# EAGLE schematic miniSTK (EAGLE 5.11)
ALTERNATIV: BLM21PG331; ARTIKEL: ABM7-14.7456MHZ-D2Y; COPYRIGHT: © 2013 Leo-Andres Hofmann; LICENSE: CC-BY-SA 3.0; MATERIAL: NP0/C0G; PROJEKT: miniSTK; REVISION: 1.1; TEXT-1: Prototypenbereich; TEXT-2: LEDs & Taster; TEXT-3: Erweiterungsanschluss; TEXT-5: Referenzwiderstände: 1%; TOLERANZ: 1%; TP_SIGNAL_NAME: MP-1

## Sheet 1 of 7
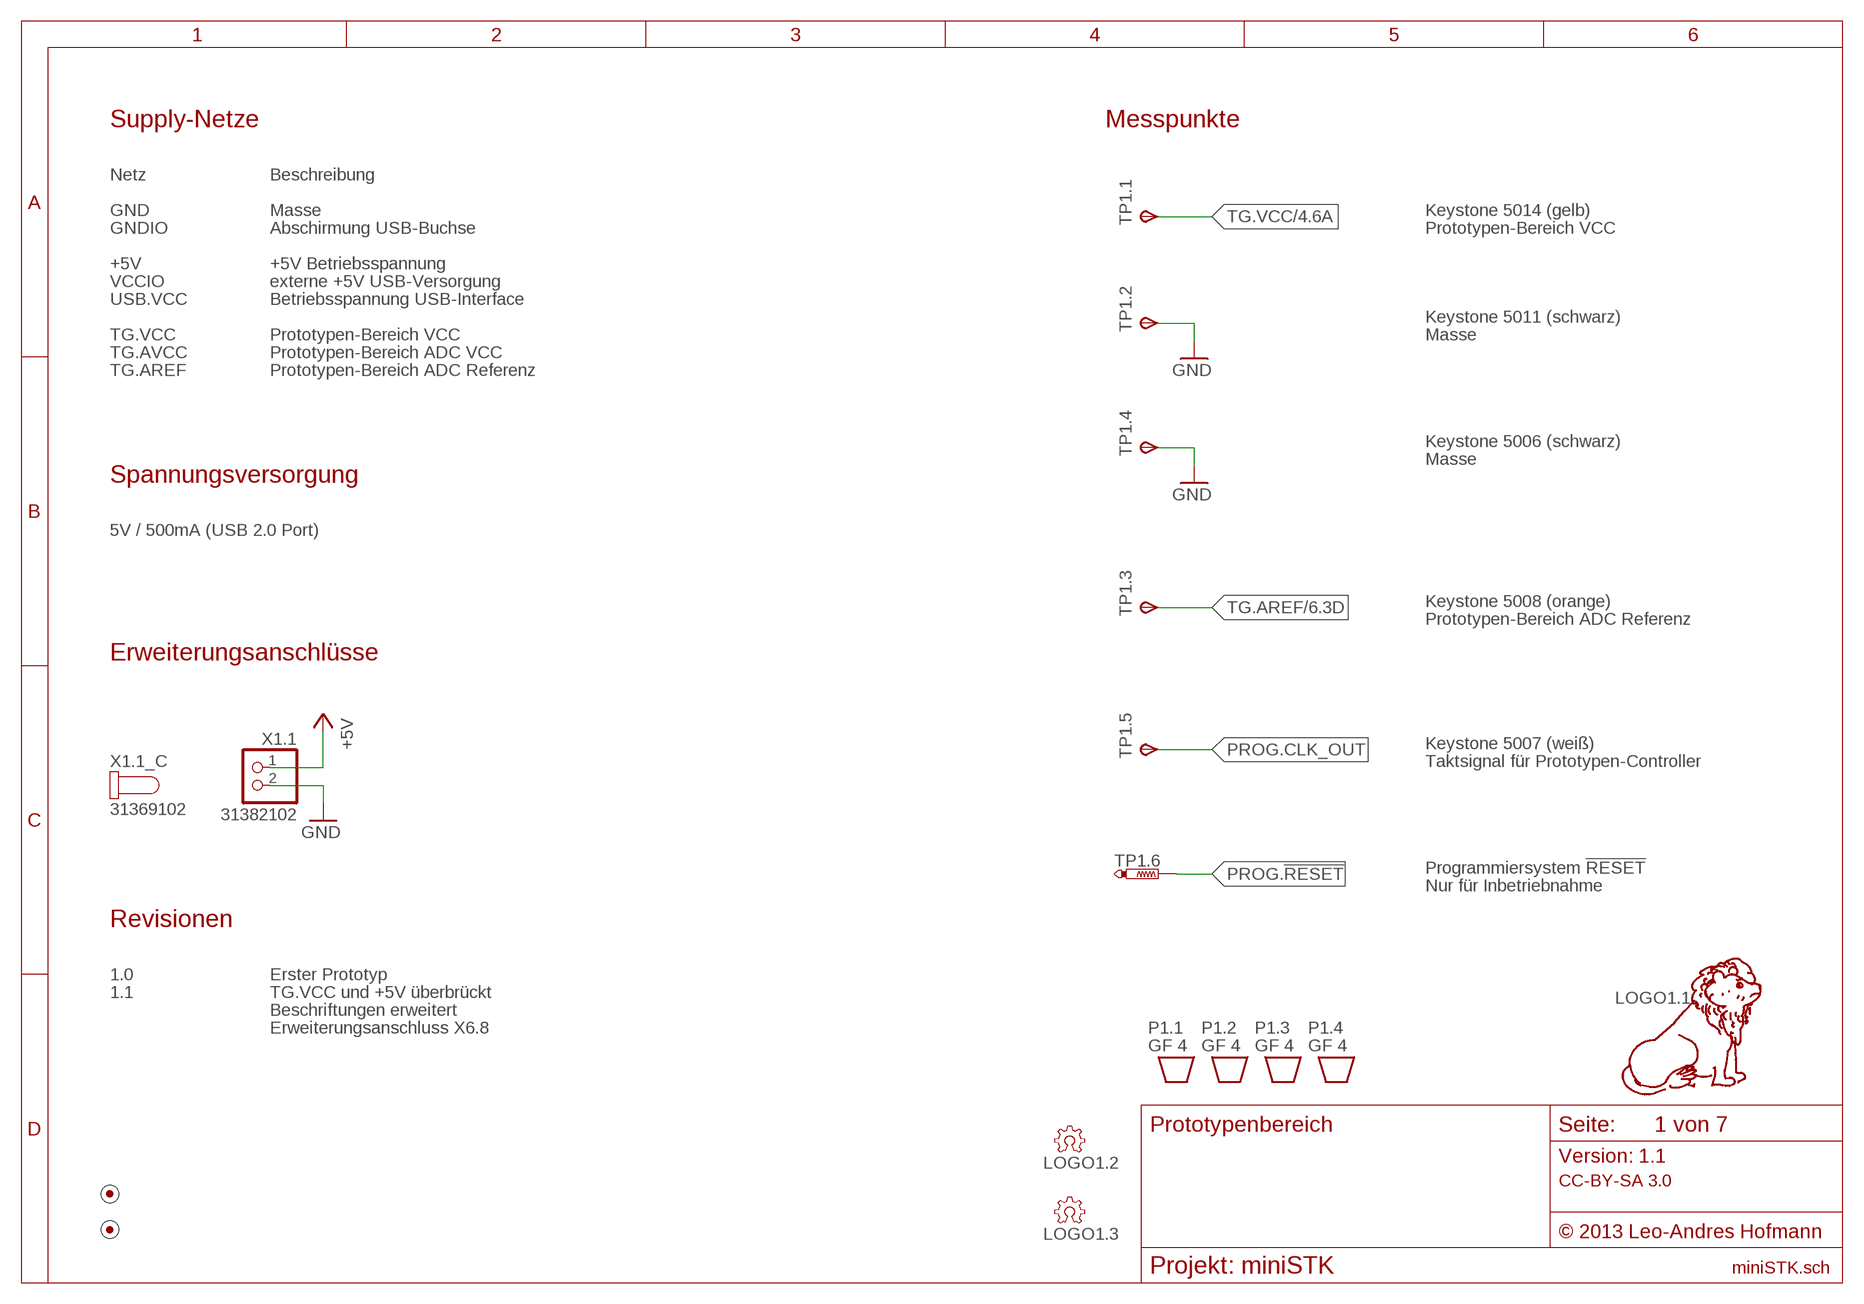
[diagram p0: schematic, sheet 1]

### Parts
LOGO1.1  LOGO-10MM-TPLACE  [10MM-TPLACE]
LOGO1.2  OSHW-3MM-FILL-TSTOP  [OSHW-FILL-3MM-TSTOP]
LOGO1.3  OSHW-3MM-FILL-TPLACE  [OSHW-FILL-3MM-TPLACE]
MARK1  FIDUCIAL-1.0/CREAM  [FIDUCIAL-1MM/CREAM]
MARK2  FIDUCIAL-1.0/CREAM  [FIDUCIAL-1MM/CREAM]
P1.1  GF 4  PAD/GF_4/REF  [FOOT-12MM/REF]
P1.2  GF 4  PAD/GF_4/REF  [FOOT-12MM/REF]
P1.3  GF 4  PAD/GF_4/REF  [FOOT-12MM/REF]
P1.4  GF 4  PAD/GF_4/REF  [FOOT-12MM/REF]
TP1.1  5014  TESTPOINT-1.6MM  [TESTPOINT-1.6MM]
TP1.2  5011  TESTPOINT-1.6MM  [TESTPOINT-1.6MM]
TP1.3  5008  TESTPOINT-1.6MM  [TESTPOINT-1.6MM]
TP1.4  5006  TESTPOINT-1.6MM  [TESTPOINT-1.6MM]
TP1.5  5007  TESTPOINT-1.6MM  [TESTPOINT-1.6MM]
TP1.6  PTR1TP15R  [TP15R]
X1.1  31382102  1PIN-2-31382102  [31382102]

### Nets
+5V: X1.1.1 ; also sheet 2,3,4,5,6,7
GND: TP1.2.TP(PP) TP1.4.TP(PP) X1.1.2 ; also sheet 2,3,4,5,6,7
PROG.!RESET: TP1.6.TP ; also sheet 4
PROG.CLK_OUT [Taktsignale]: TP1.5.TP(PP) ; also sheet 4
TG.AREF: TP1.3.TP(PP) ; also sheet 6
TG.VCC: TP1.1.TP(PP) ; also sheet 4,5,6,7

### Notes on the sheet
- Supply-Netze | Messpunkte
- Netz | Beschreibung
- GND | Masse | Keystone 5014 (gelb)
- GNDIO | Abschirmung USB-Buchse | Prototypen-Bereich VCC
- +5V | +5V Betriebsspannung
- VCCIO | externe +5V USB-Versorgung
- USB.VCC | Betriebsspannung USB-Interface
- Keystone 5011 (schwarz)
- TG.VCC | Prototypen-Bereich VCC | Masse
- TG.AVCC | Prototypen-Bereich ADC VCC
- TG.AREF | Prototypen-Bereich ADC Referenz
- Keystone 5006 (schwarz)
- Masse
- Spannungsversorgung
- 5V / 500mA (USB 2.0 Port)
- Keystone 5008 (orange)
- Prototypen-Bereich ADC Referenz
- Erweiterungsanschlüsse
- Keystone 5007 (weiß)
- Taktsignal für Prototypen-Controller
- Programmiersystem !RESET
- Nur für Inbetriebnahme
- Revisionen
- 1.0 | Erster Prototyp
- 1.1 | TG.VCC und +5V überbrückt
- Beschriftungen erweitert
- Erweiterungsanschluss X6.8

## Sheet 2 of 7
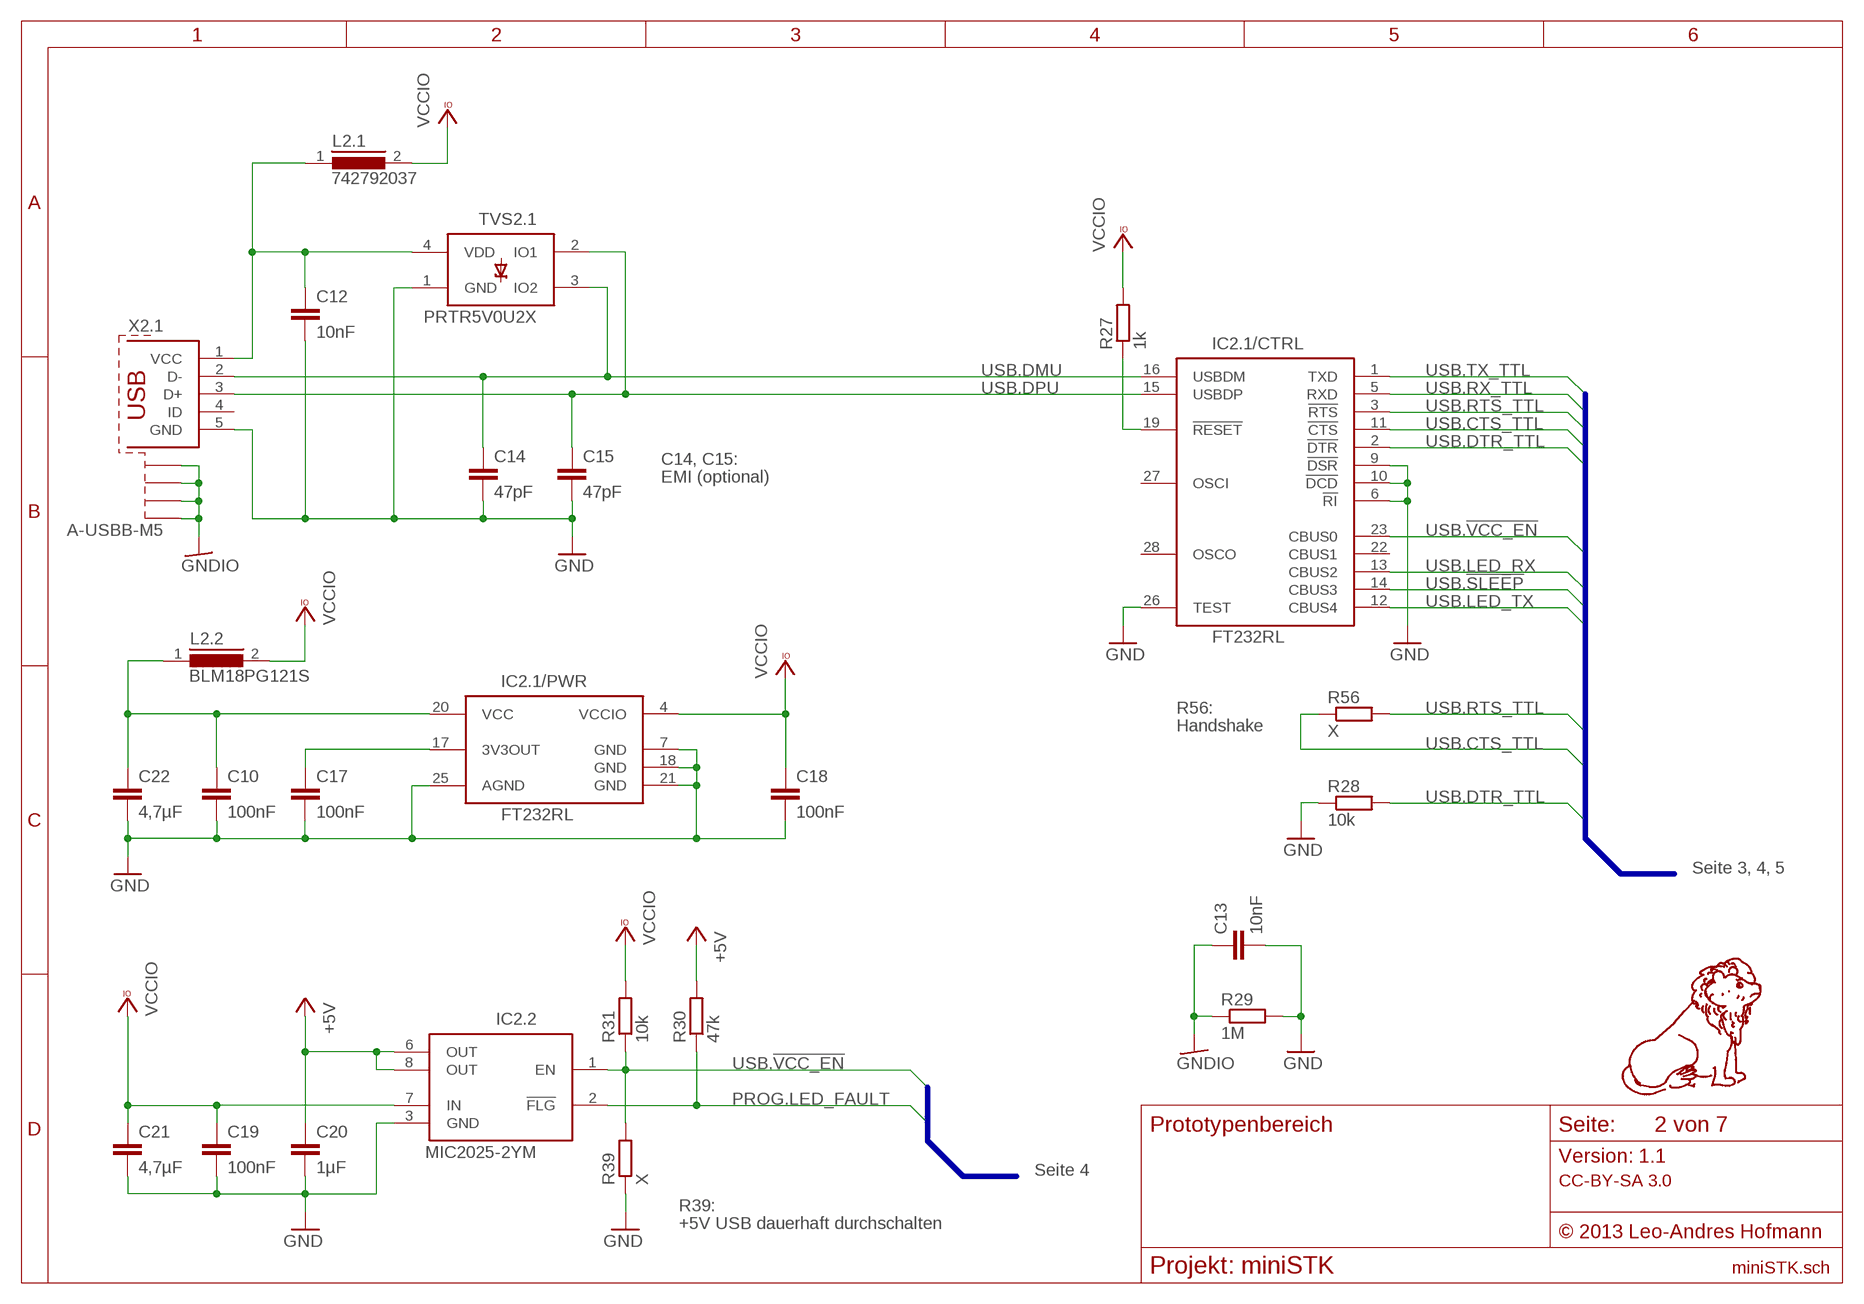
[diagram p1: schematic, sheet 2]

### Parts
C10  100nF  C-0603  [C-0603]
C12  10nF  C-0805  [C-0805]
C13  10nF  C-0805  [C-0805]
C14  47pF  C-0603  [C-0603]
C15  47pF  C-0603  [C-0603]
C17  100nF  C-0603  [C-0603]
C18  100nF  C-0603  [C-0603]
C19  100nF  C-0603  [C-0603]
C20  1µF  C-0603  [C-0603]
C21  4,7µF  C-0805  [C-0805]
C22  4,7µF  C-0805  [C-0805]
IC2.1  FT232RL  [SSOP28]
IC2.2  MIC2025-2YM  MIC2025-XYM  [SOIC8]
L2.1  742792037  INDUCTOR-WE-CBF-0805  [WE-CBF-0805]
L2.2  BLM18PG121S  INDUCTOR-BLM18  [BLM18]
R27  1k  R-0603  [R-0603]
R28  10k  R-0603  [R-0603]
R29  1M  R-0805  [R-0805]
R30  47k  R-0603  [R-0603]
R31  10k  R-0603  [R-0603]
R39  X  R-0603  [R-0603]
R56  X  R-0603  [R-0603]
TVS2.1  PRTR5V0U2X  2-ARRAY-NXP-PRTR  [SOT143B]
X2.1  A-USBB-M5  A-USBB-M5/SMD  [MINI-USB-B-SMD]

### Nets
3V3OUT: C17.1 IC2.1.17(/PWR:3V3OUT)
+5V: C20.1 IC2.2.6(OUT) IC2.2.8(OUT) R30.2 ; also sheet 1,3,4,5,6,7
GND: C10.2 C12.2 C13.2 C14.2 C15.2 C17.2 C18.2 C19.2 C20.2 C21.2 C22.2 IC2.1.6(/CTRL:!RI) IC2.1.7(/PWR:GND) IC2.1.9(/CTRL:!DSR) IC2.1.10(/CTRL:!DCD) IC2.1.18(/PWR:GND) IC2.1.21(/PWR:GND) IC2.1.25(/PWR:AGND) IC2.1.26(/CTRL:TEST) IC2.2.3(GND) R28.1 R29.2 R39.1 TVS2.1.1(GND) X2.1.5(GND) ; also sheet 1,3,4,5,6,7
GNDIO [IO-Schirm]: C13.1 R29.1 X2.1.S1(SHIELD) X2.1.S2(SHIELD) X2.1.S3(SHIELD) X2.1.S4(SHIELD)
IC2.1/!RESET: IC2.1.19(/CTRL:!RESET) R27.1
N$25: C12.1 L2.1.1 TVS2.1.4(VDD) X2.1.1(VCC)
PROG.LED_FAULT: IC2.2.2(!FLG) R30.1 ; also sheet 4,5
USB.!SLEEP: IC2.1.14(/CTRL:CBUS3) ; also sheet 5
USB.!VCC_EN: IC2.1.23(/CTRL:CBUS0) IC2.2.1(EN) R31.1 R39.2
USB.CTS_TTL: IC2.1.11(/CTRL:!CTS) R56.1 ; also sheet 5
USB.DMU [USB Datenleitungen]: C14.1 IC2.1.16(/CTRL:USBDM) TVS2.1.3(IO2) X2.1.2(D-)
USB.DPU [USB Datenleitungen]: C15.1 IC2.1.15(/CTRL:USBDP) TVS2.1.2(IO1) X2.1.3(D+)
USB.DTR_TTL: IC2.1.2(/CTRL:!DTR) R28.2 ; also sheet 4
USB.LED_RX: IC2.1.13(/CTRL:CBUS2) ; also sheet 5
USB.LED_TX: IC2.1.12(/CTRL:CBUS4) ; also sheet 5
USB.RTS_TTL: IC2.1.3(/CTRL:!RTS) R56.2 ; also sheet 5
USB.RX_TTL: IC2.1.5(/CTRL:RXD) ; also sheet 3
USB.TX_TTL: IC2.1.1(/CTRL:TXD) ; also sheet 3
USB.VCC: C10.1 C22.1 IC2.1.20(/PWR:VCC) L2.2.1
VCCIO: C18.1 C19.1 C21.1 IC2.1.4(/PWR:VCCIO) IC2.2.7(IN) L2.1.2 L2.2.2 R27.2 R31.2 ; also sheet 4,5
Unconnected: IC2.1.22(/CTRL:CBUS1) IC2.1.27(/CTRL:OSCI) IC2.1.28(/CTRL:OSCO) X2.1.4(ID)

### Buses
USB:USB.TX_TTL,USB.RX_TTL,USB.RTS_TTL,USB.CTS_TTL,USB.DTR_TTL,USB.!VCC_EN,USB.!SLEEP,USB.LED_TX,USB.LED_RX
USB:USB.!VCC_EN,PROG.LED_FAULT

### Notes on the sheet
- C14, C15:
- EMI (optional)
- R56:
- Handshake
- Seite 3, 4, 5
- Seite 4
- R39:
- +5V USB dauerhaft durchschalten

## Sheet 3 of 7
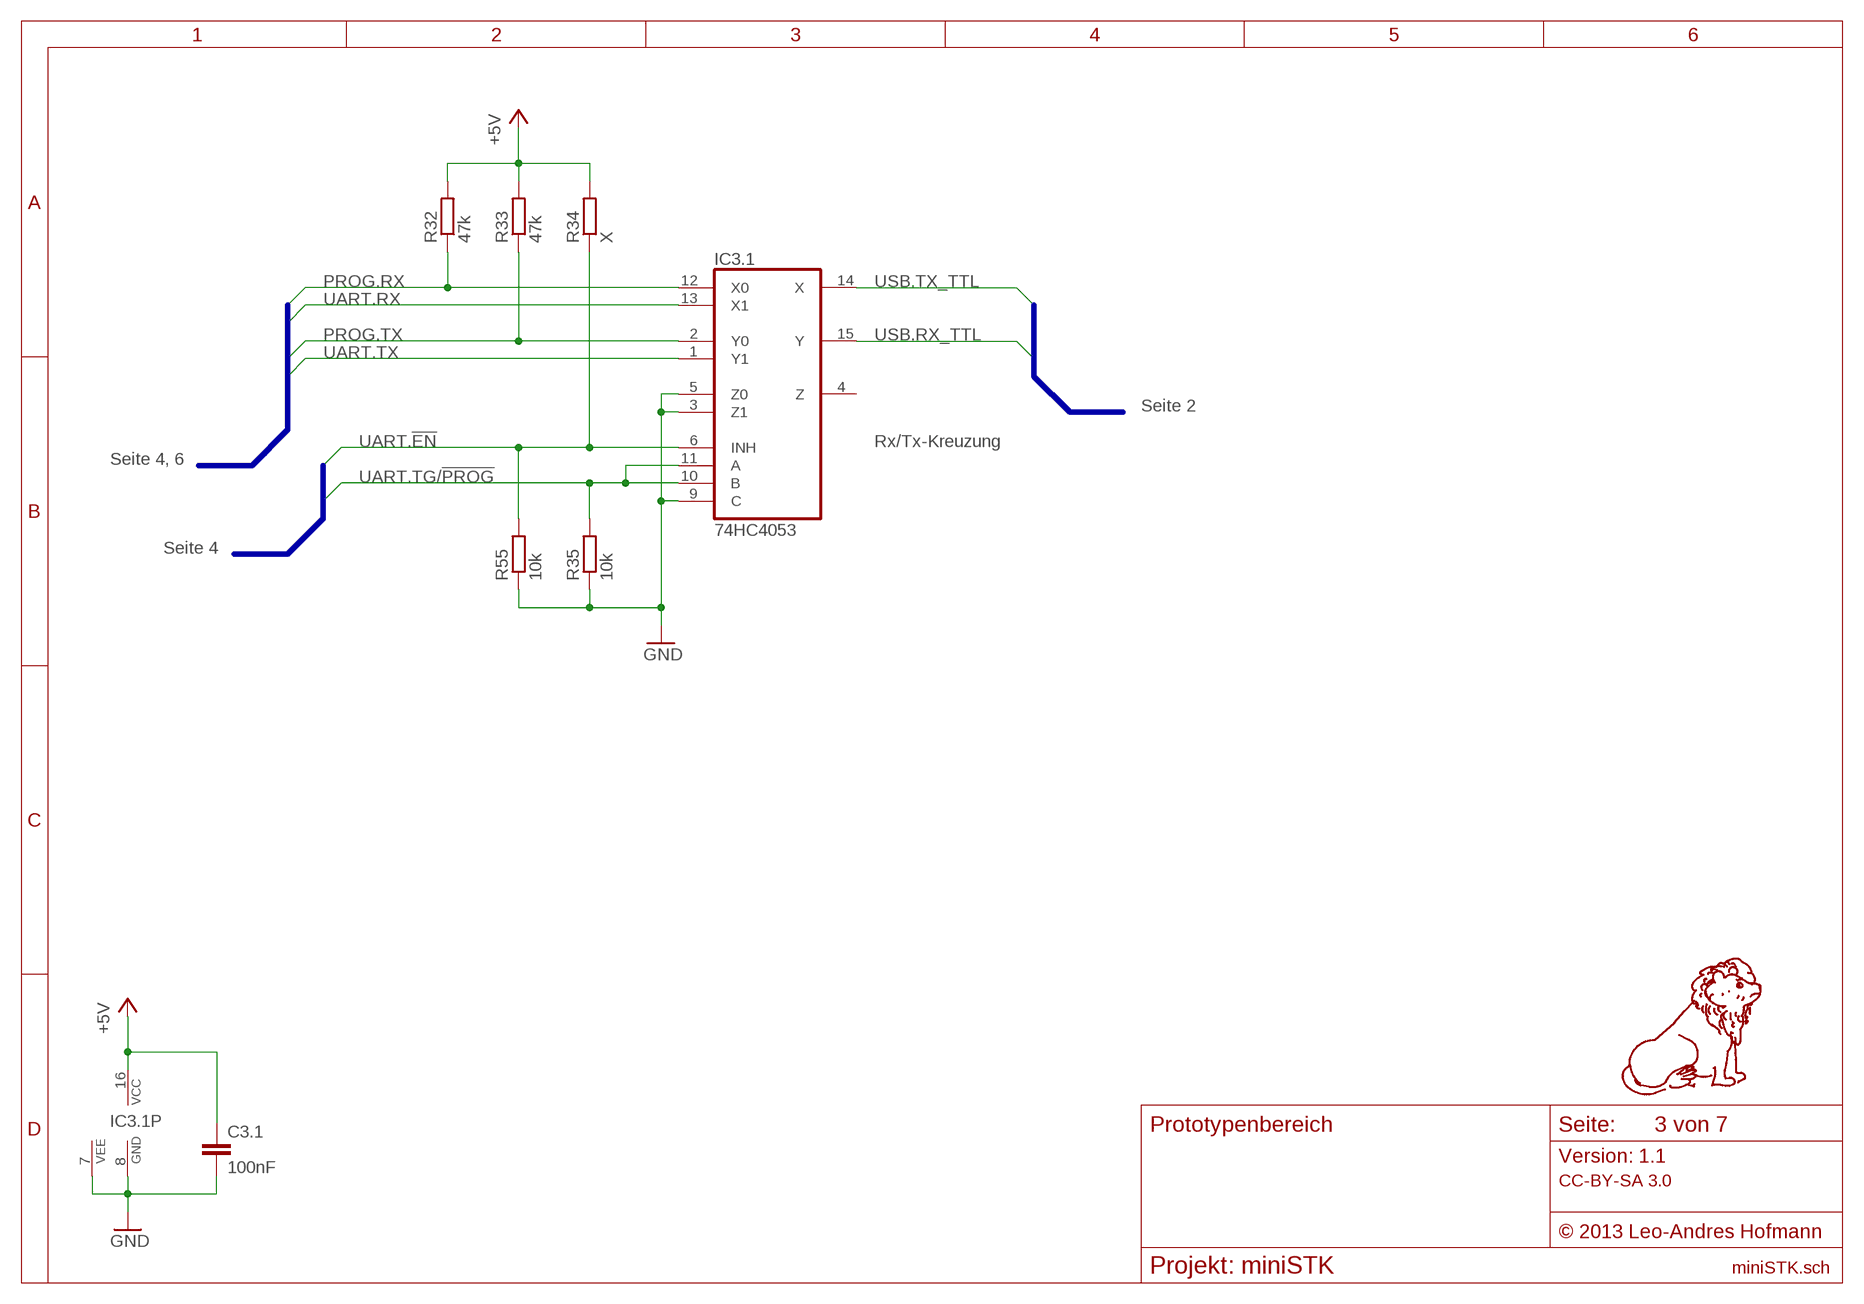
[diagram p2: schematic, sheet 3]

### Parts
C3.1  100nF  C-0603  [C-0603]
IC3.1  74HC4053  4053D  [SO16]
R32  47k  R-0603  [R-0603]
R33  47k  R-0603  [R-0603]
R34  X  R-0603  [R-0603]
R35  10k  R-0603  [R-0603]
R55  10k  R-0603  [R-0603]

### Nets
+5V: C3.1.1 IC3.1.16(VCC) R32.2 R33.2 R34.2 ; also sheet 1,2,4,5,6,7
GND: C3.1.2 IC3.1.3(Z1) IC3.1.5(Z0) IC3.1.7(VEE) IC3.1.8(GND) IC3.1.9(C) R35.1 R55.1 ; also sheet 1,2,4,5,6,7
PROG.RX: IC3.1.12(X0) R32.1 ; also sheet 4
PROG.TX: IC3.1.2(Y0) R33.1 ; also sheet 4
UART.!EN: IC3.1.6(INH) R34.1 R55.2 ; also sheet 4
UART.RX: IC3.1.13(X1) ; also sheet 6
UART.TG/!PROG: IC3.1.10(B) IC3.1.11(A) R35.2 ; also sheet 4
UART.TX: IC3.1.1(Y1) ; also sheet 6
USB.RX_TTL: IC3.1.15(Y) ; also sheet 2
USB.TX_TTL: IC3.1.14(X) ; also sheet 2
Unconnected: IC3.1.4(Z)

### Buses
USB:USB.TX_TTL,USB.RX_TTL
UART:UART.!EN,UART.TG/!PROG
UART:PROG.RX,PROG.TX,UART.RX,UART.TX

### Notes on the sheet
- Seite 2
- Rx/Tx-Kreuzung
- Seite 4, 6
- Seite 4

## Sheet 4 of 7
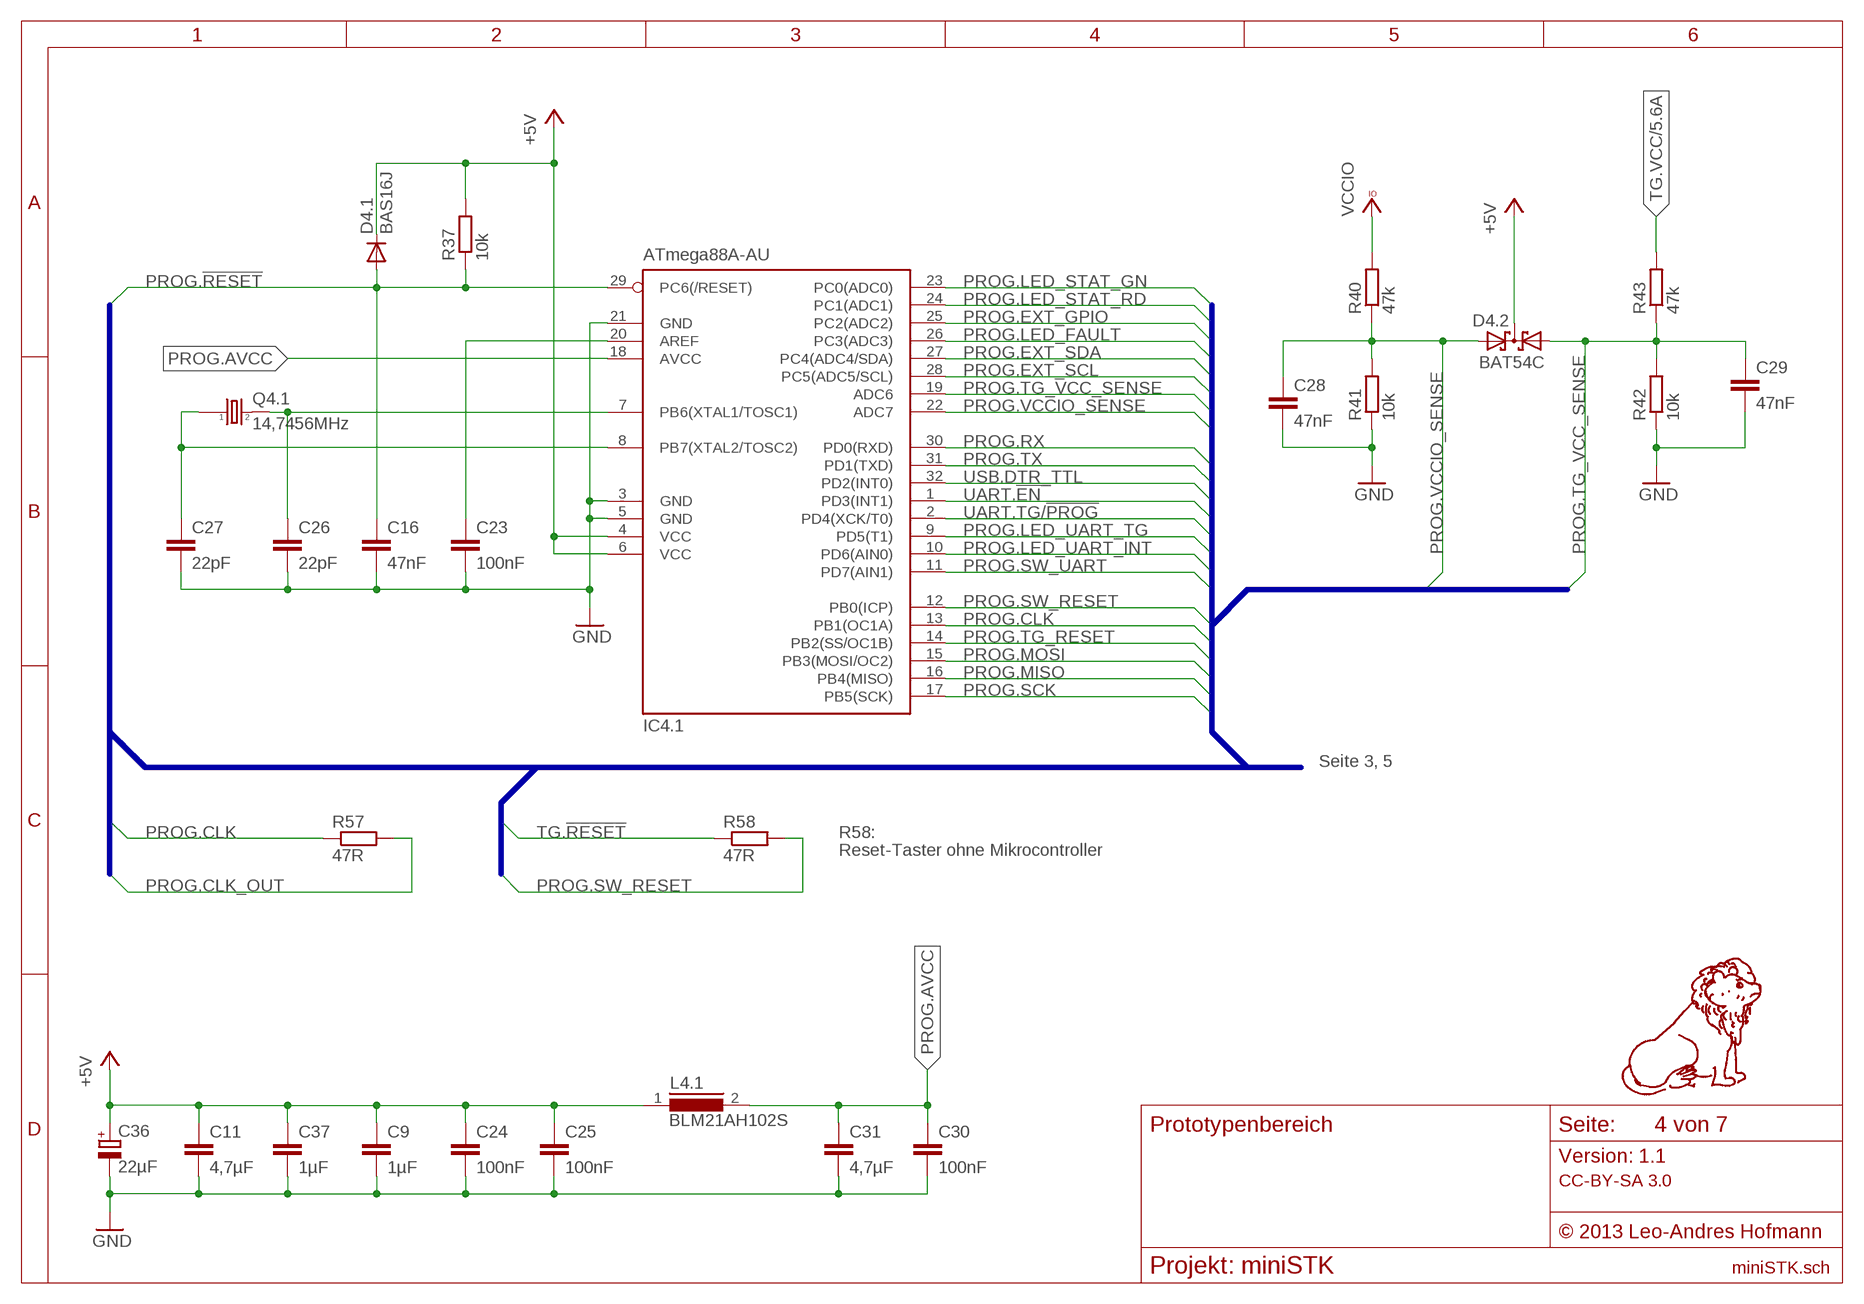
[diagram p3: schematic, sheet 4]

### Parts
C9  1µF  C-0603  [C-0603]
C11  4,7µF  C-0805  [C-0805]
C16  47nF  C-0603  [C-0603]
C23  100nF  C-0603  [C-0603]
C24  100nF  C-0603  [C-0603]
C25  100nF  C-0603  [C-0603]
C26  22pF  C-0603  [C-0603]
C27  22pF  C-0603  [C-0603]
C28  47nF  C-0603  [C-0603]
C29  47nF  C-0603  [C-0603]
C30  100nF  C-0603  [C-0603]
C31  4,7µF  C-0805  [C-0805]
C36  22µF  CPOL-EUB  [PANASONIC_B]
C37  1µF  C-0603  [C-0603]
D4.1  BAS16J  DIODE-SOD323  [DIODE-SOD323]
D4.2  BAT54C  [SOT23]
IC4.1  ATmega88A-AU  MEGA8-AI  [TQFP32-08]
L4.1  BLM21AH102S  INDUCTOR-BLM21  [BLM21]
Q4.1  14,7456MHz  CRYSTAL-ABM7  [CRYSTAL-ABM7]
R37  10k  R-0603  [R-0603]
R40  47k  R-0603  [R-0603]
R41  10k  R-0603  [R-0603]
R42  10k  R-0603  [R-0603]
R43  47k  R-0603  [R-0603]
R57  47R  R-0603  [R-0603]
R58  47R  R-0603  [R-0603]

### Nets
+5V: C9.1 C11.1 C24.1 C25.1 C36.+ C37.1 D4.1.C D4.2.3(CC) IC4.1.4(VCC) IC4.1.6(VCC) L4.1.1 R37.2 ; also sheet 1,2,3,5,6,7
GND: C9.2 C11.2 C16.2 C23.2 C24.2 C25.2 C26.2 C27.2 C28.2 C29.2 C30.2 C31.2 C36.- C37.2 IC4.1.3(GND) IC4.1.5(GND) IC4.1.21(GND) R41.1 R42.1 ; also sheet 1,2,3,5,6,7
N$28: C26.1 IC4.1.7(PB6(XTAL1/TOSC1)) Q4.1.2
N$29: C23.1 IC4.1.20(AREF)
N$30: C27.1 IC4.1.8(PB7(XTAL2/TOSC2)) Q4.1.1
PROG.!RESET: C16.1 D4.1.A IC4.1.29(PC6(/RESET)) R37.1 ; also sheet 1
PROG.AVCC: C30.1 C31.1 IC4.1.18(AVCC) L4.1.2
PROG.CLK [Taktsignale]: IC4.1.13(PB1(OC1A)) R57.1
PROG.CLK_OUT [Taktsignale]: R57.2 ; also sheet 1
PROG.EXT_GPIO: IC4.1.25(PC2(ADC2)) ; also sheet 5
PROG.EXT_SCL: IC4.1.28(PC5(ADC5/SCL)) ; also sheet 5
PROG.EXT_SDA: IC4.1.27(PC4(ADC4/SDA)) ; also sheet 5
PROG.LED_FAULT: IC4.1.26(PC3(ADC3)) ; also sheet 2,5
PROG.LED_STAT_GN: IC4.1.23(PC0(ADC0)) ; also sheet 5
PROG.LED_STAT_RD: IC4.1.24(PC1(ADC1)) ; also sheet 5
PROG.LED_UART_INT: IC4.1.10(PD6(AIN0)) ; also sheet 5
PROG.LED_UART_TG: IC4.1.9(PD5(T1)) ; also sheet 5
PROG.MISO: IC4.1.16(PB4(MISO)) ; also sheet 5
PROG.MOSI: IC4.1.15(PB3(MOSI/OC2)) ; also sheet 5
PROG.RX: IC4.1.30(PD0(RXD)) ; also sheet 3
PROG.SCK: IC4.1.17(PB5(SCK)) ; also sheet 5
PROG.SW_RESET: IC4.1.12(PB0(ICP)) R58.2 ; also sheet 5
PROG.SW_UART: IC4.1.11(PD7(AIN1)) ; also sheet 5
PROG.TG_RESET: IC4.1.14(PB2(SS/OC1B)) ; also sheet 5
PROG.TG_VCC_SENSE: C29.1 D4.2.1(A1) IC4.1.19(ADC6) R42.2 R43.1
PROG.TX: IC4.1.31(PD1(TXD)) ; also sheet 3
PROG.VCCIO_SENSE: C28.1 D4.2.2(A2) IC4.1.22(ADC7) R40.1 R41.2
TG.!RESET: R58.1 ; also sheet 5,6
TG.VCC: R43.2 ; also sheet 1,5,6,7
UART.!EN: IC4.1.1(PD3(INT1)) ; also sheet 3
UART.TG/!PROG: IC4.1.2(PD4(XCK/T0)) ; also sheet 3
USB.DTR_TTL: IC4.1.32(PD2(INT0)) ; also sheet 2
VCCIO: R40.2 ; also sheet 2,5

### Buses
PROG:PROG.!RESET,PROG.RX,PROG.TX,USB.!VCC_FAULT,USB.DTR_TTL,UART.!EN,UART.TG/!PROG,PROG.MOSI,PROG.MISO,PROG.SCK,PROG.TG_RESET,PROG.VCCIO_SENSE,PROG.TG_VCC_SENSE,PROG.CLK,PROG.SW_UART,PROG.SW_RESET,PROG.EXT_SDA,PROG.EXT_SCL,PROG.EXT_GPIO,PROG.LED_STAT_RD,PROG.LED_STAT_GN,PROG.LED_UART_TG,PROG.LED_UART_INT,PROG.LED_FAULT,PROG.CLK_OUT,TG.!RESET

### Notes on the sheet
- Seite 3, 5
- R58:
- Reset-Taster ohne Mikrocontroller

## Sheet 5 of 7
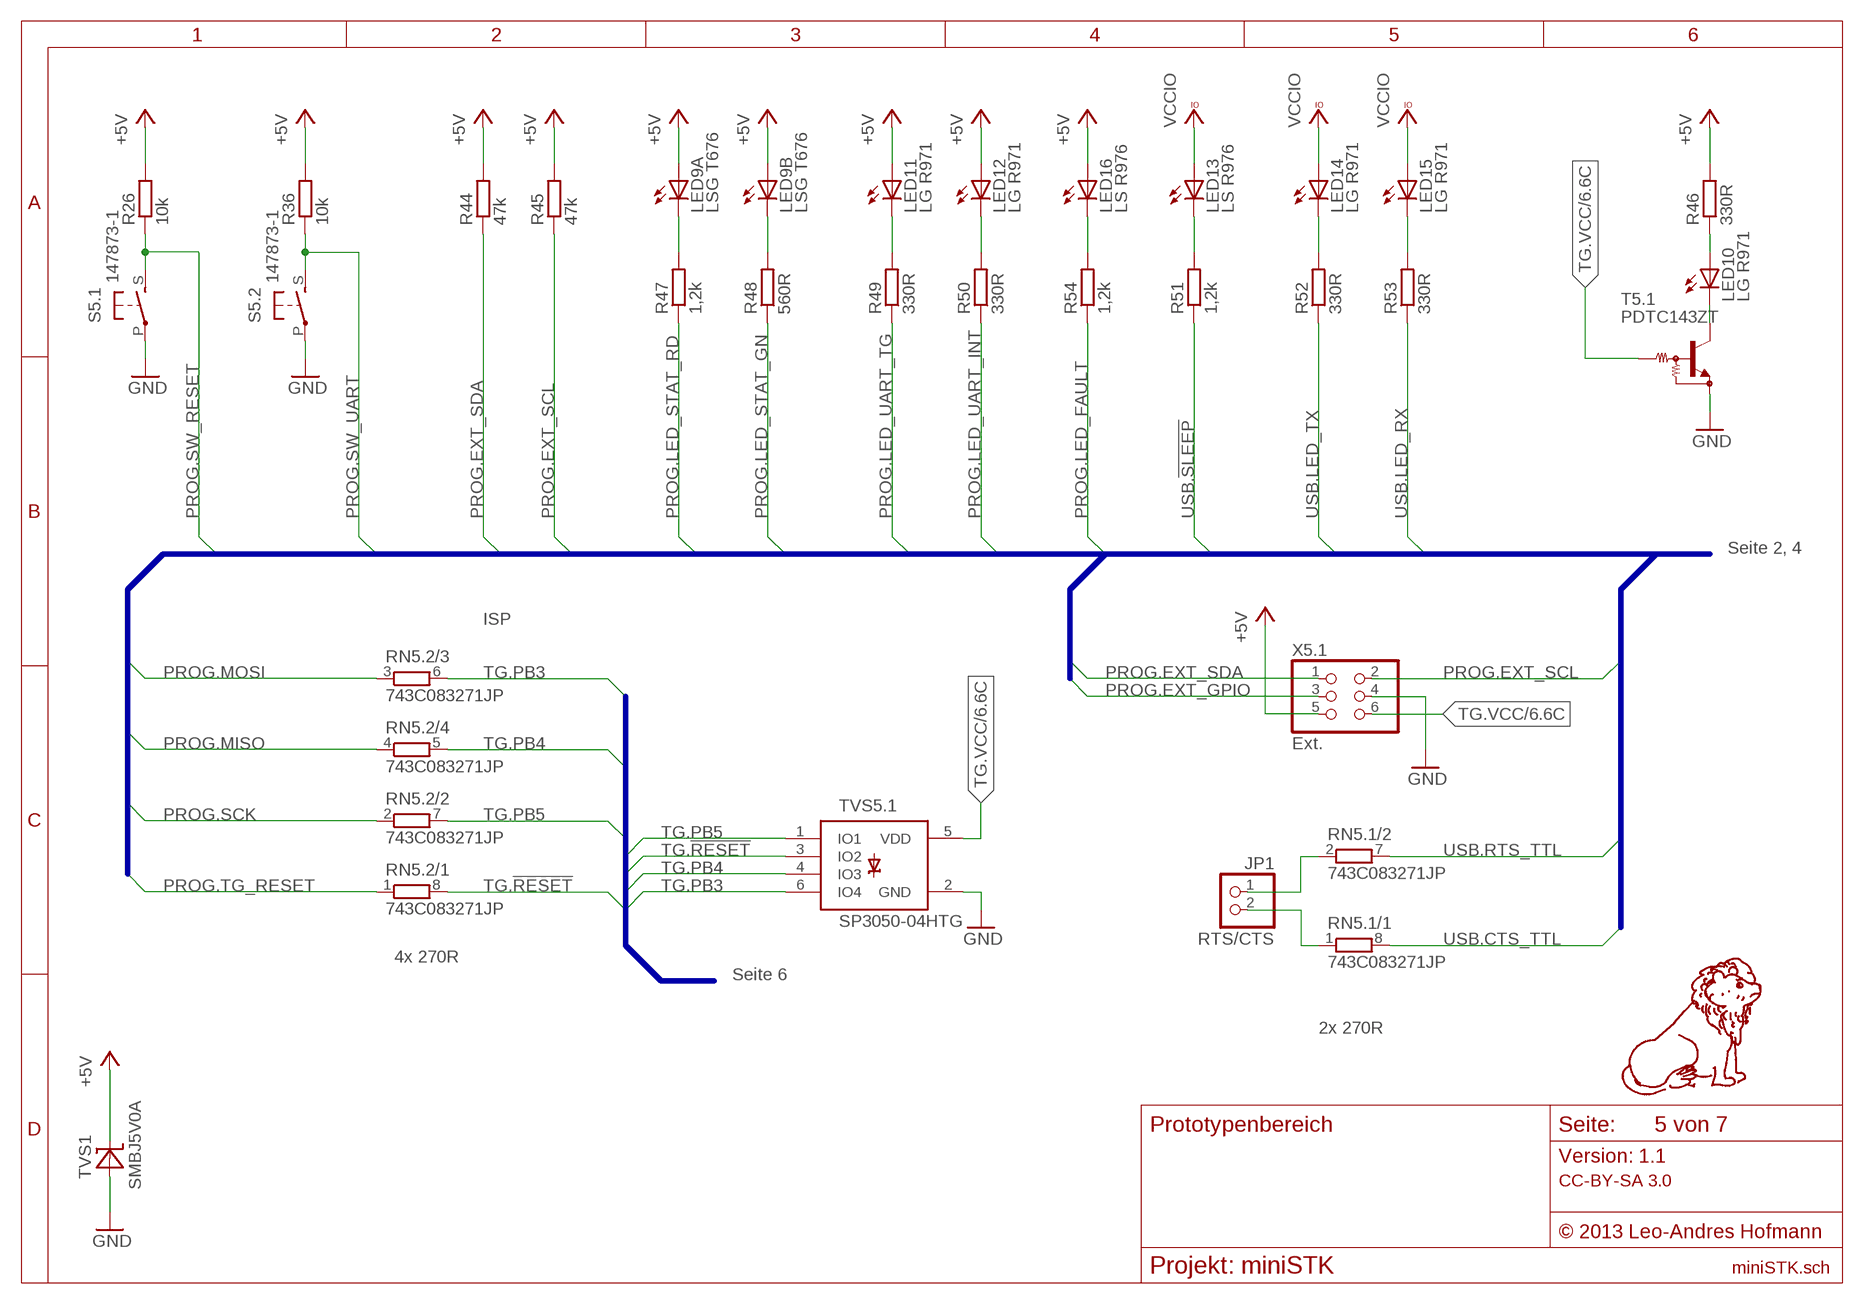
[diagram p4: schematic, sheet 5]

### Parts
JP1  RTS/CTS  PINHD-1X2  [1X02]
LED9  LSG T676  LED-DUO-TOPLED-DUO-S  [OSRAM-TOPLED_2-S]
LED10  LG R971  LED-CHIPLED-0805  [CHIPLED-0805]
LED11  LG R971  LED-CHIPLED-0805  [CHIPLED-0805]
LED12  LG R971  LED-CHIPLED-0805  [CHIPLED-0805]
LED13  LS R976  LED-CHIPLED-0805  [CHIPLED-0805]
LED14  LG R971  LED-CHIPLED-0805  [CHIPLED-0805]
LED15  LG R971  LED-CHIPLED-0805  [CHIPLED-0805]
LED16  LS R976  LED-CHIPLED-0805  [CHIPLED-0805]
R26  10k  R-0603  [R-0603]
R36  10k  R-0603  [R-0603]
R44  47k  R-0603  [R-0603]
R45  47k  R-0603  [R-0603]
R46  330R  R-0603  [R-0603]
R47  1,2k  R-0603  [R-0603]
R48  560R  R-0603  [R-0603]
R49  330R  R-0603  [R-0603]
R50  330R  R-0603  [R-0603]
R51  1,2k  R-0603  [R-0603]
R52  330R  R-0603  [R-0603]
R53  330R  R-0603  [R-0603]
R54  1,2k  R-0603  [R-0603]
RN5.1  743C083271JP  RN4I-CTS_743C083  [743C083]
RN5.2  743C083271JP  RN4I-CTS_743C083  [743C083]
S5.1  147873-1  SWITCH-147873  [SWITCH-147873]
S5.2  147873-1  SWITCH-147873  [SWITCH-147873]
T5.1  PDTC143ZT  MUN2211T1-NPN_DRIVER-SC59-BEC  [SC59-BEC]
TVS1  SMBJ5V0A  TVS-UNI-SM6T-X-A  [DO214-AA]
TVS5.1  SP3050-04HTG  4-ARRAY-SP3050-04H  [SOT23-6_2]
X5.1  Ext.  PINHD-2X3  [2X03]

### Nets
+5V: LED9.2(A:A) LED9.4(B:A) LED11.A LED12.A LED16.A R26.2 R36.2 R44.2 R45.2 R46.2 TVS1.K X5.1.5 ; also sheet 1,2,3,4,6,7
GND: S5.1.P S5.2.P T5.1.E TVS1.A TVS5.1.2(GND) X5.1.4 ; also sheet 1,2,3,4,6,7
N$31: LED10.C T5.1.C
N$32: LED10.A R46.1
N$33: LED15.C R53.2
N$34: LED14.C R52.2
N$35: LED12.C R50.2
N$36: LED11.C R49.2
N$37: LED13.C R51.2
N$38: LED9.3(B:C) R48.2
N$39: LED9.1(A:C) R47.2
N$40: LED16.C R54.2
PROG.EXT_GPIO: X5.1.3 ; also sheet 4
PROG.EXT_SCL: R45.1 X5.1.2 ; also sheet 4
PROG.EXT_SDA: R44.1 X5.1.1 ; also sheet 4
PROG.LED_FAULT: R54.1 ; also sheet 2,4
PROG.LED_STAT_GN: R48.1 ; also sheet 4
PROG.LED_STAT_RD: R47.1 ; also sheet 4
PROG.LED_UART_INT: R50.1 ; also sheet 4
PROG.LED_UART_TG: R49.1 ; also sheet 4
PROG.MISO: RN5.2.4 ; also sheet 4
PROG.MOSI: RN5.2.3 ; also sheet 4
PROG.SCK: RN5.2.2 ; also sheet 4
PROG.SW_RESET: R26.1 S5.1.S ; also sheet 4
PROG.SW_UART: R36.1 S5.2.S ; also sheet 4
PROG.TG_RESET: RN5.2.1 ; also sheet 4
TG.!RESET: RN5.2.8 TVS5.1.3(IO2) ; also sheet 4,6
TG.PB3: RN5.2.6 TVS5.1.6(IO4) ; also sheet 6
TG.PB4: RN5.2.5 TVS5.1.4(IO3) ; also sheet 6
TG.PB5: RN5.2.7 TVS5.1.1(IO1) ; also sheet 6
TG.VCC: T5.1.B TVS5.1.5(VDD) X5.1.6 ; also sheet 1,4,6,7
UART.CTS: JP1.2 RN5.1.1
UART.RTS: JP1.1 RN5.1.2
USB.!SLEEP: R51.1 ; also sheet 2
USB.CTS_TTL: RN5.1.8 ; also sheet 2
USB.LED_RX: R53.1 ; also sheet 2
USB.LED_TX: R52.1 ; also sheet 2
USB.RTS_TTL: RN5.1.7 ; also sheet 2
VCCIO: LED13.A LED14.A LED15.A ; also sheet 2,4

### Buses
PROG:PROG.SW_UART,PROG.SW_RESET,PROG.EXT_SDA,PROG.EXT_SCL,PROG.EXT_GPIO,PROG.LED_STAT_RD,PROG.LED_STAT_GN,PROG.LED_UART_TG,PROG.LED_UART_INT,PROG.LED_FAULT,USB.RTS_TTL,USB.CTS_TTL,USB.LED_TX,USB.LED_RX,USB.!SLEEP,PROG.TG_RESET,PROG.MOSI,PROG.MISO,PROG.SCK,PROG.CLK
TG:TG.PB4,TG.PB5,TG.!RESET,TG.PB3

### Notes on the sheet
- Seite 2, 4
- ISP
- 4x 270R
- Seite 6
- 2x 270R

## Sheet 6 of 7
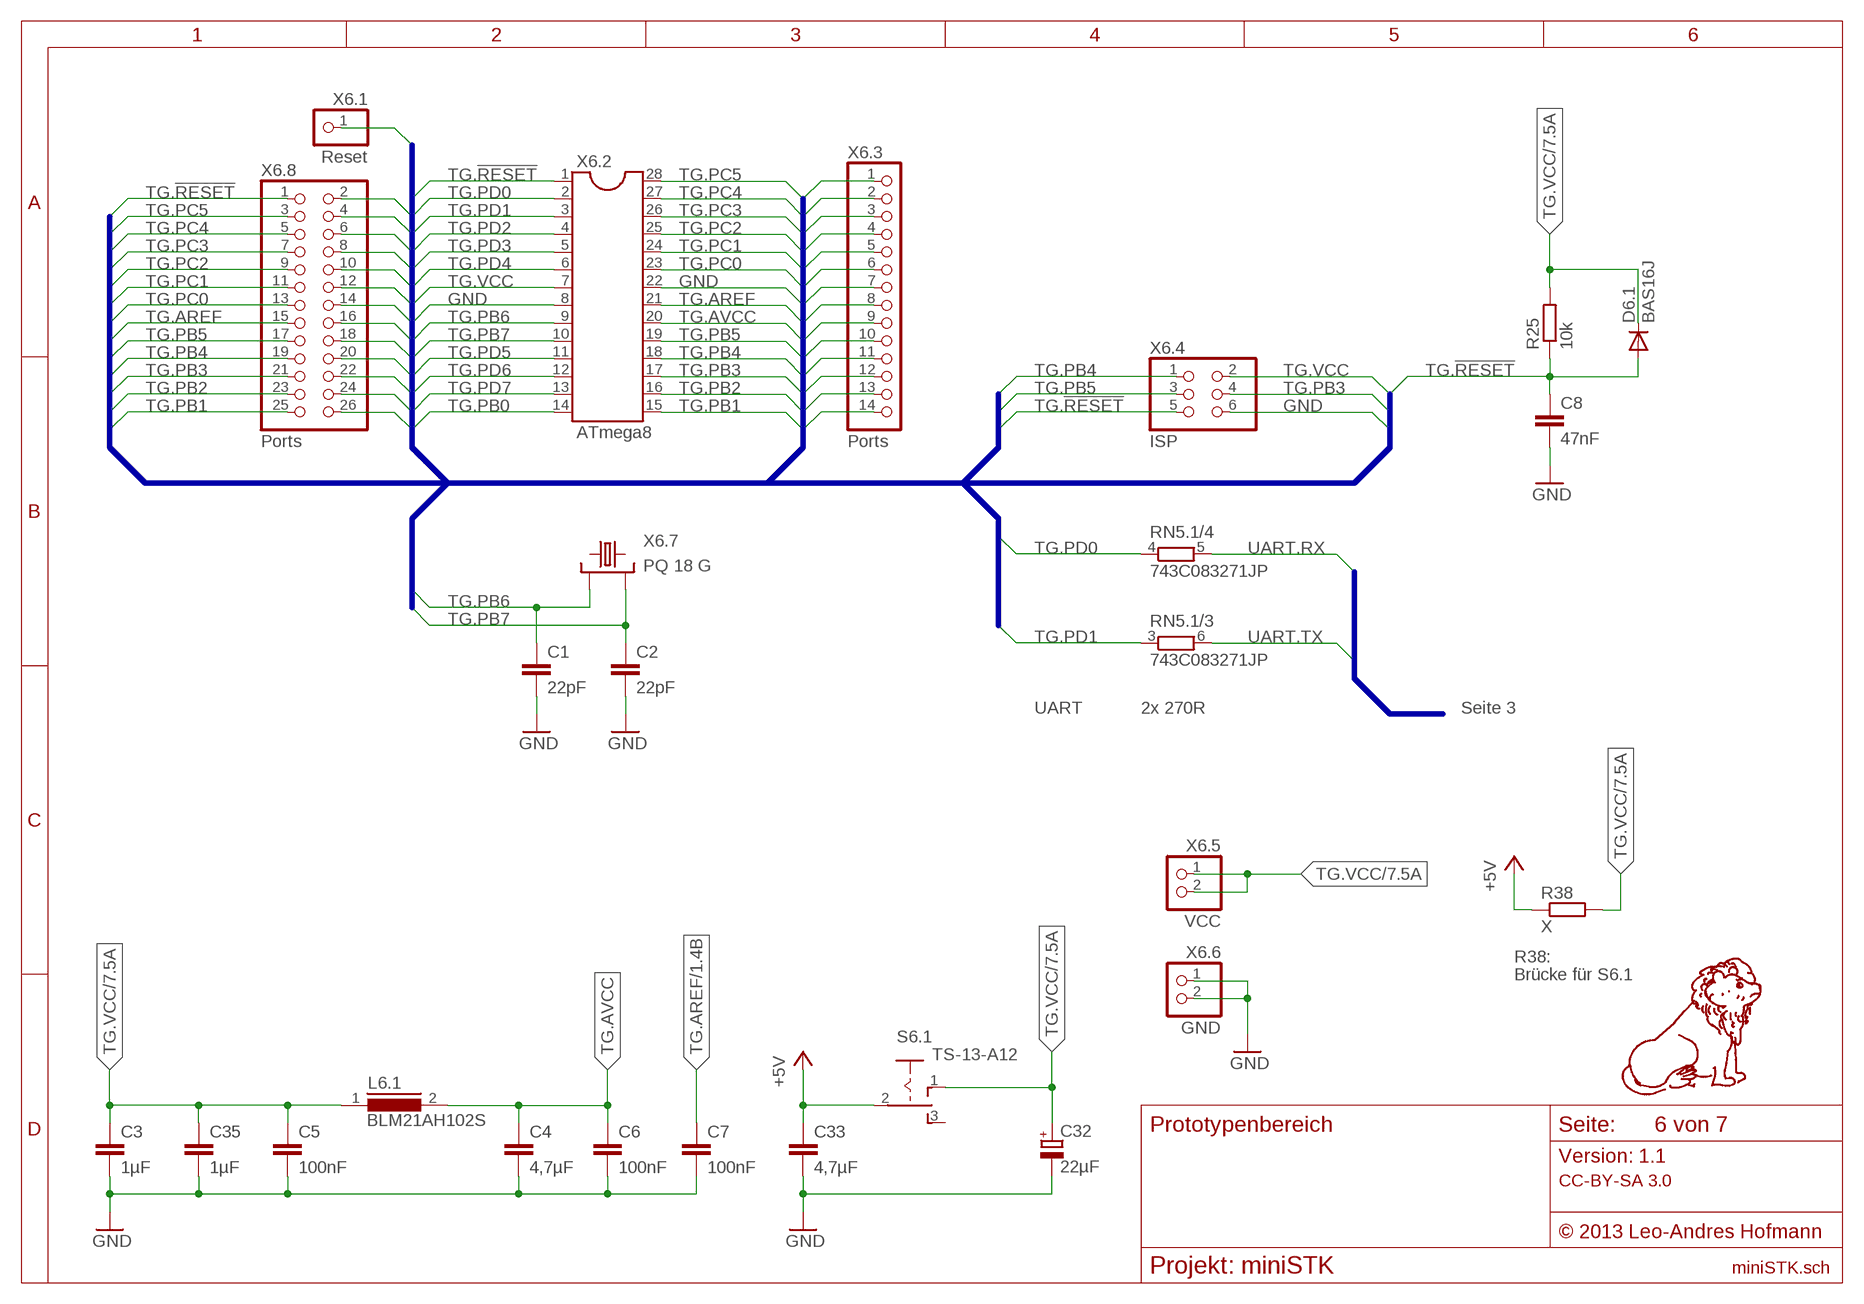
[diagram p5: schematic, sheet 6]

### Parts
C1  22pF  C-0603  [C-0603]
C2  22pF  C-0603  [C-0603]
C3  1µF  C-0603  [C-0603]
C4  4,7µF  C-0805  [C-0805]
C5  100nF  C-0603  [C-0603]
C6  100nF  C-0603  [C-0603]
C7  100nF  C-0603  [C-0603]
C8  47nF  C-0603  [C-0603]
C32  22µF  CPOL-EUB  [PANASONIC_B]
C33  4,7µF  C-0805  [C-0805]
C35  1µF  C-0603  [C-0603]
D6.1  BAS16J  DIODE-SOD323  [DIODE-SOD323]
L6.1  BLM21AH102S  INDUCTOR-BLM21  [BLM21]
R25  10k  R-0603  [R-0603]
R38  X  R-0805  [R-0805]
S6.1  TS-13-A12  SWITCH-SPDT-TS-13-XX-X-C  [TS-13-XX-X-C]
X6.1  Reset  PINHD-1X1  [1X01]
X6.2  ATmega8  DIL28-3  [DIL28-3]
X6.3  Ports  PINHD-1X14  [1X14]
X6.4  ISP  PINHD-2X3  [2X03]
X6.5  VCC  PINHD-1X2  [1X02]
X6.6  GND  PINHD-1X2  [1X02]
X6.7  PQ 18 G  CRYSTAL-SOCKET/PQ_18_X  [PQ_18_X]
X6.8  Ports  PINHD-2X13  [2X13]

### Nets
+5V: C33.1 R38.1 S6.1.2 ; also sheet 1,2,3,4,5,7
GND: C1.2 C2.2 C3.2 C4.2 C5.2 C6.2 C7.2 C8.2 C32.- C33.2 C35.2 X6.2.8 X6.2.22 X6.3.7 X6.4.6 X6.6.1 X6.6.2 X6.8.14 ; also sheet 1,2,3,4,5,7
TG.!RESET: C8.1 D6.1.A R25.1 X6.1.1 X6.2.1 X6.4.5 X6.8.1 ; also sheet 4,5
TG.AREF: C7.1 X6.2.21 X6.3.8 X6.8.15 ; also sheet 1
TG.AVCC: C4.1 C6.1 L6.1.2 X6.2.20 X6.3.9
TG.PB0: X6.2.14 X6.8.26
TG.PB1: X6.2.15 X6.3.14 X6.8.25
TG.PB2: X6.2.16 X6.3.13 X6.8.23
TG.PB3: X6.2.17 X6.3.12 X6.4.4 X6.8.21 ; also sheet 5
TG.PB4: X6.2.18 X6.3.11 X6.4.1 X6.8.19 ; also sheet 5
TG.PB5: X6.2.19 X6.3.10 X6.4.3 X6.8.17 ; also sheet 5
TG.PB6 [Taktsignale]: C1.1 X6.2.9 X6.7.1 X6.8.16
TG.PB7 [Taktsignale]: C2.1 X6.2.10 X6.7.2 X6.8.18
TG.PC0: X6.2.23 X6.3.6 X6.8.13
TG.PC1: X6.2.24 X6.3.5 X6.8.11
TG.PC2: X6.2.25 X6.3.4 X6.8.9
TG.PC3: X6.2.26 X6.3.3 X6.8.7
TG.PC4: X6.2.27 X6.3.2 X6.8.5
TG.PC5: X6.2.28 X6.3.1 X6.8.3
TG.PD0: RN5.1.4 X6.2.2 X6.8.2
TG.PD1: RN5.1.3 X6.2.3 X6.8.4
TG.PD2: X6.2.4 X6.8.6
TG.PD3: X6.2.5 X6.8.8
TG.PD4: X6.2.6 X6.8.10
TG.PD5: X6.2.11 X6.8.20
TG.PD6: X6.2.12 X6.8.22
TG.PD7: X6.2.13 X6.8.24
TG.VCC: C3.1 C5.1 C32.+ C35.1 D6.1.C L6.1.1 R25.2 R38.2 S6.1.1 X6.2.7 X6.4.2 X6.5.1 X6.5.2 X6.8.12 ; also sheet 1,4,5,7
UART.RX: RN5.1.5 ; also sheet 3
UART.TX: RN5.1.6 ; also sheet 3
Unconnected: S6.1.3

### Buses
TG:GND,TG.VCC,TG.!RESET,TG.AREF,TG.AVCC,TG.PB0,TG.PB1,TG.PB2,TG.PB3,TG.PB4,TG.PB5,TG.PB6,TG.PB7,TG.PC0,TG.PC1,TG.PC2,TG.PC3,TG.PC4,TG.PC5,TG.PD0,TG.PD1,TG.PD2,TG.PD3,TG.PD4,TG.PD5,TG.PD6,TG.PD7
UART:UART.TX,UART.RX

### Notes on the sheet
- UART | 2x 270R | Seite 3
- R38:
- Brücke für S6.1

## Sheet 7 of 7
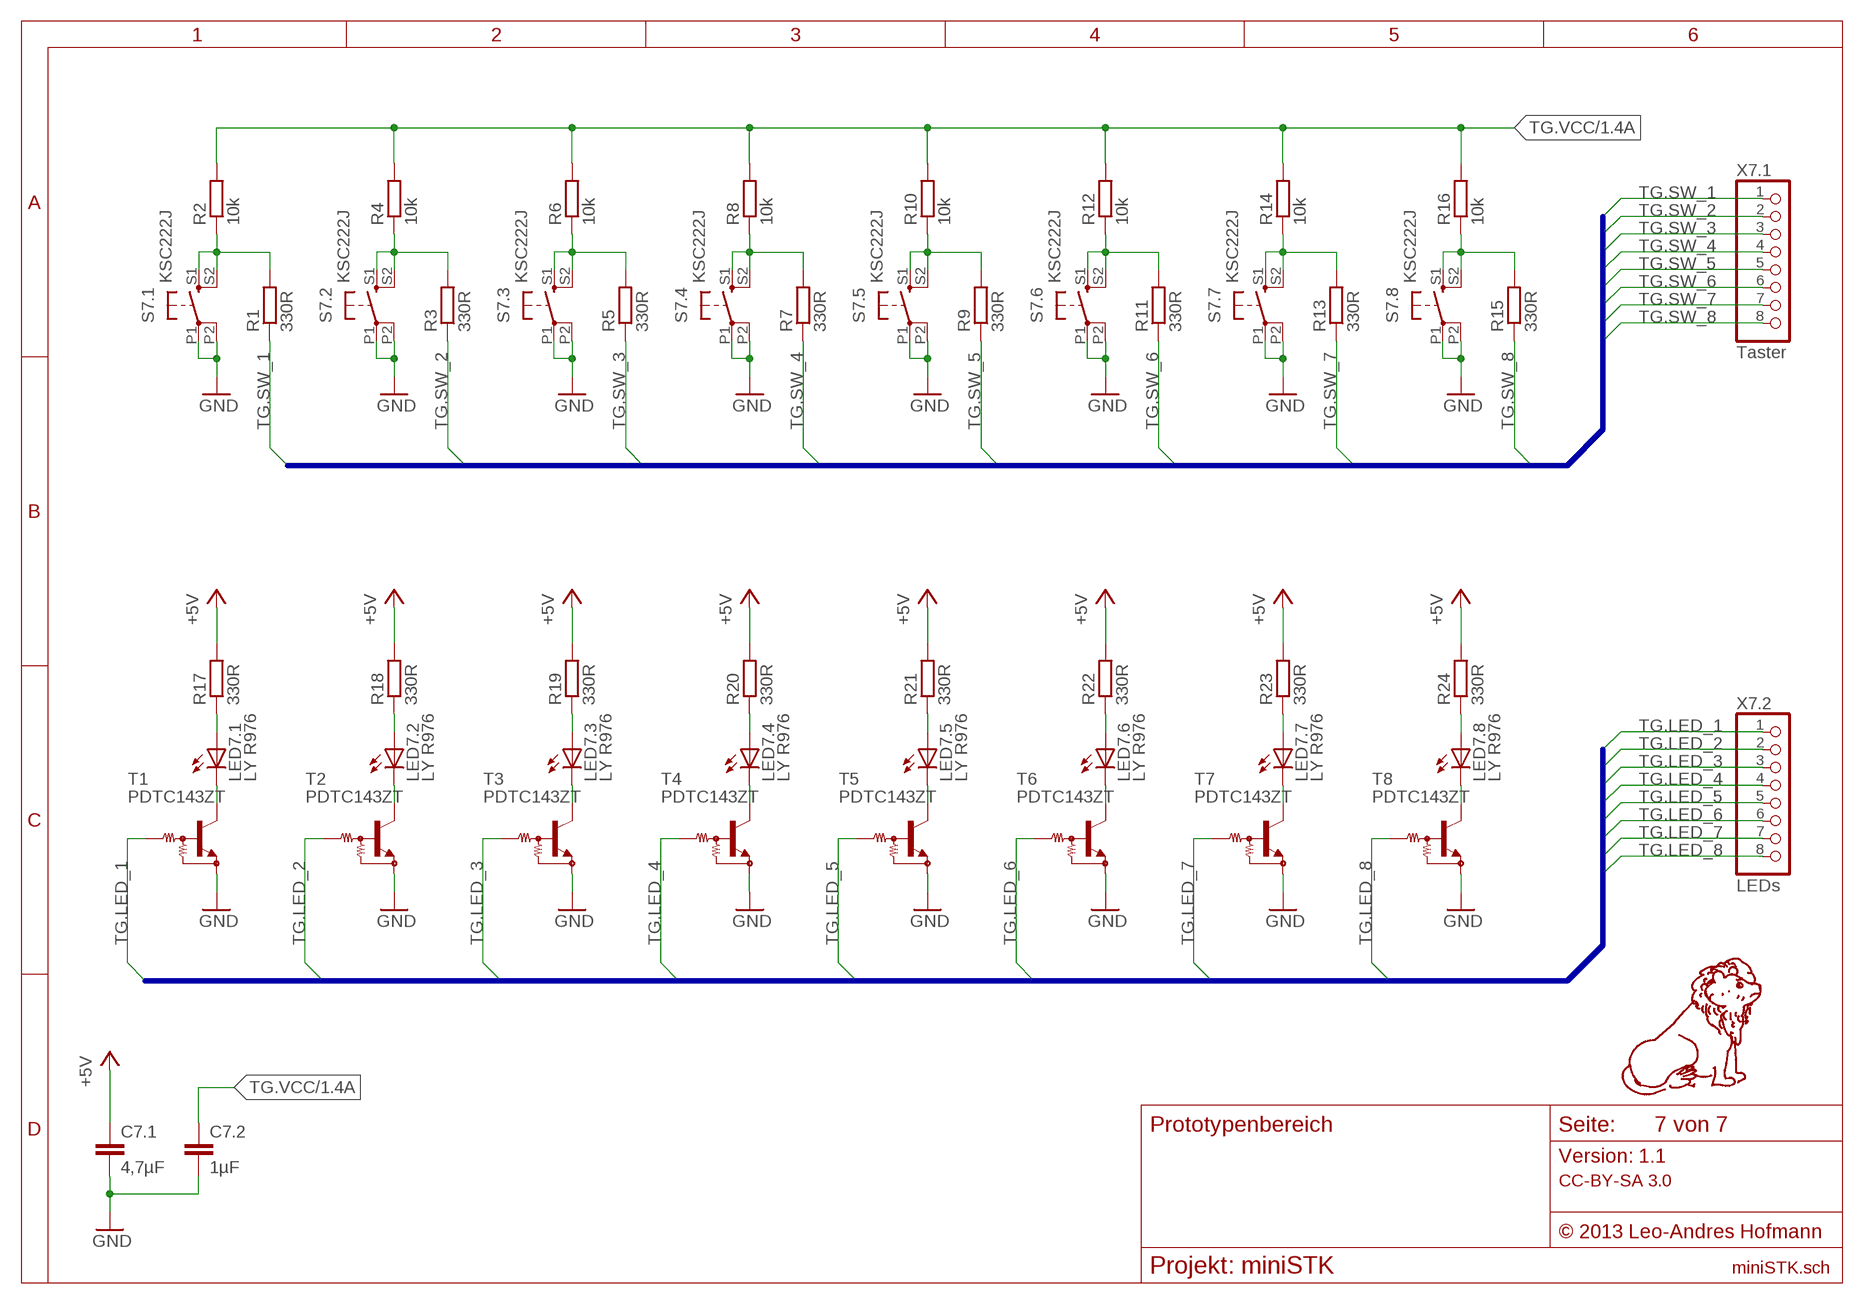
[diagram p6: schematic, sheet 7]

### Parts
C7.1  4,7µF  C-0805  [C-0805]
C7.2  1µF  C-0603  [C-0603]
LED7.1  LY R976  LED-CHIPLED-0805  [CHIPLED-0805]
LED7.2  LY R976  LED-CHIPLED-0805  [CHIPLED-0805]
LED7.3  LY R976  LED-CHIPLED-0805  [CHIPLED-0805]
LED7.4  LY R976  LED-CHIPLED-0805  [CHIPLED-0805]
LED7.5  LY R976  LED-CHIPLED-0805  [CHIPLED-0805]
LED7.6  LY R976  LED-CHIPLED-0805  [CHIPLED-0805]
LED7.7  LY R976  LED-CHIPLED-0805  [CHIPLED-0805]
LED7.8  LY R976  LED-CHIPLED-0805  [CHIPLED-0805]
R1  330R  R-0603  [R-0603]
R2  10k  R-0603  [R-0603]
R3  330R  R-0603  [R-0603]
R4  10k  R-0603  [R-0603]
R5  330R  R-0603  [R-0603]
R6  10k  R-0603  [R-0603]
R7  330R  R-0603  [R-0603]
R8  10k  R-0603  [R-0603]
R9  330R  R-0603  [R-0603]
R10  10k  R-0603  [R-0603]
R11  330R  R-0603  [R-0603]
R12  10k  R-0603  [R-0603]
R13  330R  R-0603  [R-0603]
R14  10k  R-0603  [R-0603]
R15  330R  R-0603  [R-0603]
R16  10k  R-0603  [R-0603]
R17  330R  R-0603  [R-0603]
R18  330R  R-0603  [R-0603]
R19  330R  R-0603  [R-0603]
R20  330R  R-0603  [R-0603]
R21  330R  R-0603  [R-0603]
R22  330R  R-0603  [R-0603]
R23  330R  R-0603  [R-0603]
R24  330R  R-0603  [R-0603]
S7.1  KSC222J  SWITCH-2-KSC-J  [KSC-SW-J]
S7.2  KSC222J  SWITCH-2-KSC-J  [KSC-SW-J]
S7.3  KSC222J  SWITCH-2-KSC-J  [KSC-SW-J]
S7.4  KSC222J  SWITCH-2-KSC-J  [KSC-SW-J]
S7.5  KSC222J  SWITCH-2-KSC-J  [KSC-SW-J]
S7.6  KSC222J  SWITCH-2-KSC-J  [KSC-SW-J]
S7.7  KSC222J  SWITCH-2-KSC-J  [KSC-SW-J]
S7.8  KSC222J  SWITCH-2-KSC-J  [KSC-SW-J]
T1  PDTC143ZT  MUN2211T1-NPN_DRIVER-SC59-BEC  [SC59-BEC]
T2  PDTC143ZT  MUN2211T1-NPN_DRIVER-SC59-BEC  [SC59-BEC]
T3  PDTC143ZT  MUN2211T1-NPN_DRIVER-SC59-BEC  [SC59-BEC]
T4  PDTC143ZT  MUN2211T1-NPN_DRIVER-SC59-BEC  [SC59-BEC]
T5  PDTC143ZT  MUN2211T1-NPN_DRIVER-SC59-BEC  [SC59-BEC]
T6  PDTC143ZT  MUN2211T1-NPN_DRIVER-SC59-BEC  [SC59-BEC]
T7  PDTC143ZT  MUN2211T1-NPN_DRIVER-SC59-BEC  [SC59-BEC]
T8  PDTC143ZT  MUN2211T1-NPN_DRIVER-SC59-BEC  [SC59-BEC]
X7.1  Taster  PINHD-1X8  [1X08]
X7.2  LEDs  PINHD-1X8  [1X08]

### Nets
+5V: C7.1.1 R17.2 R18.2 R19.2 R20.2 R21.2 R22.2 R23.2 R24.2 ; also sheet 1,2,3,4,5,6
GND: C7.1.2 C7.2.2 S7.1.P1(P) S7.1.P2(P) S7.2.P1(P) S7.2.P2(P) S7.3.P1(P) S7.3.P2(P) S7.4.P1(P) S7.4.P2(P) S7.5.P1(P) S7.5.P2(P) S7.6.P1(P) S7.6.P2(P) S7.7.P1(P) S7.7.P2(P) S7.8.P1(P) S7.8.P2(P) T1.E T2.E T3.E T4.E T5.E T6.E T7.E T8.E ; also sheet 1,2,3,4,5,6
N$1: R15.2 R16.1 S7.8.S1(S) S7.8.S2(S)
N$2: R13.2 R14.1 S7.7.S1(S) S7.7.S2(S)
N$3: R11.2 R12.1 S7.6.S1(S) S7.6.S2(S)
N$4: R9.2 R10.1 S7.5.S1(S) S7.5.S2(S)
N$5: R7.2 R8.1 S7.4.S1(S) S7.4.S2(S)
N$6: R5.2 R6.1 S7.3.S1(S) S7.3.S2(S)
N$7: R3.2 R4.1 S7.2.S1(S) S7.2.S2(S)
N$8: R1.2 R2.1 S7.1.S1(S) S7.1.S2(S)
N$9: LED7.1.A R17.1
N$10: LED7.2.A R18.1
N$11: LED7.3.A R19.1
N$12: LED7.4.A R20.1
N$13: LED7.5.A R21.1
N$14: LED7.6.A R22.1
N$15: LED7.7.A R23.1
N$16: LED7.8.A R24.1
N$17: LED7.8.C T8.C
N$18: LED7.7.C T7.C
N$19: LED7.6.C T6.C
N$20: LED7.5.C T5.C
N$21: LED7.4.C T4.C
N$22: LED7.3.C T3.C
N$23: LED7.2.C T2.C
N$24: LED7.1.C T1.C
TG.LED_1: T1.B X7.2.1
TG.LED_2: T2.B X7.2.2
TG.LED_3: T3.B X7.2.3
TG.LED_4: T4.B X7.2.4
TG.LED_5: T5.B X7.2.5
TG.LED_6: T6.B X7.2.6
TG.LED_7: T7.B X7.2.7
TG.LED_8: T8.B X7.2.8
TG.SW_1: R1.1 X7.1.1
TG.SW_2: R3.1 X7.1.2
TG.SW_3: R5.1 X7.1.3
TG.SW_4: R7.1 X7.1.4
TG.SW_5: R9.1 X7.1.5
TG.SW_6: R11.1 X7.1.6
TG.SW_7: R13.1 X7.1.7
TG.SW_8: R15.1 X7.1.8
TG.VCC: C7.2.1 R2.2 R4.2 R6.2 R8.2 R10.2 R12.2 R14.2 R16.2 ; also sheet 1,4,5,6

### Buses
SWITCHES:TG.SW_1,TG.SW_2,TG.SW_3,TG.SW_4,TG.SW_5,TG.SW_6,TG.SW_7,TG.SW_8
LEDS:TG.LED_1,TG.LED_2,TG.LED_3,TG.LED_4,TG.LED_5,TG.LED_6,TG.LED_7,TG.LED_8

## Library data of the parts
C1-C3 C3.1 C4-C7 C7.1 C7.2 C8-C31 C33 C35 C37 = leo_rc-smd:C: Capacitor
C32 C36 = rcl:CPOL-EU: POLARIZED CAPACITOR, European symbol
D4.1 D6.1 = leo_misc-smd:DIODE: SMD Diode
D4.2 = diode:BAT54C: Schottky Diodes Source: Fairchild .. BAT54.pdf
IC2.1 = leo_chip-ftdi-usb-uart:FT232R: FTDI FT232R USB UART
IC2.2 = leo_chip-micrel-power:MIC2025-X: Micrel Power Distribution Switch Single Channel -1: Active High -2: Active Low
IC3.1 = 40xx:4053: Triple 2-channel ANALOG MULTIPLEXER
IC4.1 = atmel:MEGA8: MICROCONTROLLER 8 Kbytes FLASH, 1 kbytes SRAM, 512 bytes EEPROM, USART, 6-channel 10 bit ADC, 2-channel 8 bit ADC Pin compatible with Atmega48, ATMega88, ATMega168 Source: avr.lbr; MPN: ATMEGA8-16AU; OC_FARNELL: 9171371; OC_NEWARK: 73M8863
JP1 X6.5 X6.6 = pinhead:PINHD-1X2: PIN HEADER
L2.1 = leo_inductor-wuerth:INDUCTOR: Würth SMD Inductor
L2.2 L4.1 L6.1 = leo_inductor-fastron:INDUCTOR: Fastron SMD Inductor
LED7.1-LED7.8 LED10-LED16 = leo_misc-smd:LED: SMD LED
LED9 = leo_misc-smd:LED-DUO: SMD Duo LED
LOGO1.1 = leo_misc-logo:LOGO: leo-andres.de PCB Logo
LOGO1.2 LOGO1.3 = leo_misc-logo:OSHW: OSHW Logo
MARK1 MARK2 = leo_misc-logo:FIDUCIAL: Fiducial
P1.1-P1.4 = leo_misc-smd:PAD: Self-adhevise rubber/foam foot</bS
Q4.1 = leo_misc-smd:CRYSTAL: 2 Pad Crystal
R1-R58 = leo_rc-smd:R: Resistor
RN5.1 RN5.2 = leo_resistor_network:RN4I: 4 single resistors array
S5.1 S5.2 = leo_misc-smd:SWITCH: SMD Tactile Switch
S6.1 = leo_misc-tht:SWITCH-SPDT: SPDT Switch, On - None - On
S7.1-S7.8 = leo_misc-smd:SWITCH-2: SMD Tactile Switch
T1-T5 T5.1 T6-T8 = transistor:*-NPN_DRIVER-: NPN Bias Resistor Transistor
TP1.1-TP1.5 = leo_misc-tht:TESTPOINT: Keystone THT Testpoints (wire loop)
TP1.6 = testpad:PTR1: TEST PIN
TVS1 = leo_diode-tvs:TVS-UNI: TVS Diode, Unidirectional
TVS2.1 = leo_diode-tvs:2-ARRAY: Dual TVS Diode Array 2 IO-Lines + VDD
TVS5.1 = leo_diode-tvs:4-ARRAY: Quad TVS Diode Array 4 IO-Lines + VDD
X1.1 = leo_con-ria:1PIN-2: 1 Pin Header, 2 Pole
X2.1 = leo_con-usb:A-USBB-M5/SMD: Assmann Mini-USB B SMD
X5.1 X6.4 = pinhead:PINHD-2X3: PIN HEADER
X6.1 = pinhead:PINHD-1X1: PIN HEADER
X6.2 = ic-package:DIL28: Dual In Line
X6.3 = pinhead:PINHD-1X14: PIN HEADER
X6.7 = leo_misc-tht:CRYSTAL-SOCKET: Fischer Elektronik PQ 18 Crytal Socket
X6.8 = pinhead:PINHD-2X13: PIN HEADER
X7.1 X7.2 = pinhead:PINHD-1X8: PIN HEADER

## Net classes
0 Standardleiter: width 0.254 mm, drill 0.4 mm
1 USB Datenleitungen: width 0.254 mm
2 IO-Schirm: clearance 0.5 mm
3 Taktsignale: clearance 0.508 mm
